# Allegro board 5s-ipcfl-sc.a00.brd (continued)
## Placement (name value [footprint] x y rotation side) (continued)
PU80  RT9045AGSP  [MX_SOIC_8P_50_201X236_PAD]  209.55 150.01 180 top
PU581  RT3607CEGQW  [MX_QFN_56P_16_S236_PAD_4V]  78.64 218.73 0 top
PU591  RT9624DGQWA  [MX_DFN_8P_20_79X79_PAD_RIC]  70.67 186.56 180 top
PU592  RT9624DGQWA  [MX_DFN_8P_20_79X79_PAD_RIC]  67.01 205.07 180 top
PU601  RT9624DGQWA  [MX_DFN_8P_20_79X79_PAD_RIC]  70.54 169.21 180 top
PU602  RT9624DGQWA  [MX_DFN_8P_20_79X79_PAD_RIC]  71.29 152.14 180 top
PU611  RT9624DGQWA  [MX_DFN_8P_20_79X79_PAD_RIC]  95.45 227.46 270 top
PU612  RT9624DGQWA  [MX_DFN_8P_20_79X79_PAD_RIC]  147.74 228.57 180 top
PU651  RT8125CGQW  [MX_DFN_10P_20_S118_PAD_R_4V]  213.36 220.98 0 top
PU681  RT9025_25PSP  [MX_SOIC_8P_50_201X236_P_NIK]  44.12 232.26 180 top
Q3  UM6K1N  [MX_SOT363]  97.03 12.32 270 top
Q4  PMBS3904  [MX_SOT23]  105.44 7.8 90 top
Q5  UM6K1N  [MX_SOT363]  104.65 12.32 270 top
Q9  PMBS3904  [MX_SOT23]  28.24 40.89 0 top
Q35  UM6K1N  [MX_SOT363]  229.79 216.15 270 top
Q53  UM6K1N  [MX_SOT363]  215.52 139.32 0 top
R18  1K  [MX_R0402_SMALL_T01]  215.54 46.02 180 top
R19  1K  [MX_R0402_SMALL_T01]  213.92 46.02 0 top
R25  300  [MX_R0603_SMALL_T01]  103 5.69 90 top
R27  300  [MX_R0603_SMALL_T01]  99.85 5.69 90 top
R30  300  [MX_R0603_SMALL_T01]  95.15 5.69 90 top
R31  300  [MX_R0603_SMALL_T01]  101.14 5.69 90 top
R36  110  [MX_R0805_SMALL_T02_H26]  31.47 41.99 90 top
R37  100  [MX_R0402_SMALL_T01]  28.17 37.97 90 top
R636  100K  [MX_R0402_SMALL_T01]  225.55 34.29 0 top
R37456  90.9K  [MX_R0402_SMALL_T01]  222.5 105.03 90 top
R60373  45.3K  [MX_R0402_SMALL_T01]  225.7 104.75 180 top
R60374  45.3K  [MX_R0402_SMALL_T01]  223.72 116.97 90 top
R60375  90.9K  [MX_R0402_SMALL_T01]  225.59 79.68 0 top
R60381  53.6K  [MX_R0402_SMALL_T01]  222.81 116.97 90 top
R60385  53.6K  [MX_R0402_SMALL_T01]  224.43 105.03 90 top
R69583  100K  [MX_R0402_SMALL_T01]  225.6 80.64 0 top
R69584  100K  [MX_R0402_SMALL_T01]  223.47 105.03 90 top
R69686  300  [MX_R0603_SMALL_T01]  98.32 5.69 90 top
R69687  300  [MX_R0603_SMALL_T01]  96.7 5.69 90 top
R69694  2.32K  [MX_R0402_SMALL_T01]  118.19 56.13 90 top
R69695  100K  [MX_R0402_SMALL_T01]  221.5 99.26 180 top
RFC14  10PF/50V  [MX_C0402_SMALL_T01]  9.19 138.86 270 top
RFC15  10PF/50V  [MX_C0402_SMALL_T01]  21.79 139.52 90 top
RFC29  10PF/50V  [MX_C0402_SMALL_T01]  173.66 106.55 90 top
RFC30  10PF/50V  [MX_C0402_SMALL_T01]  190.63 108.97 90 top
RFC31  10PF/50V  [MX_C0402_SMALL_T01]  207.8 109.22 90 top
RFC32  10PF/50V  [MX_C0402_SMALL_T01]  206.88 109.22 90 top
RFC100  10PF/50V  [MX_C0402_SMALL_T01]  208.74 143.81 0 top
RFC101  10PF/50V  [MX_C0402_SMALL_T01]  208.84 159 90 top
RFC102  10PF/50V  [MX_C0402_SMALL_T01]  206.98 102.41 270 top
RFC103  10PF/50V  [MX_C0402_SMALL_T01]  207.82 164.59 90 top
RFC104  10PF/50V  [MX_C0402_SMALL_T01]  174.65 101.27 270 top
RFC105  10PF/50V  [MX_C0402_SMALL_T01]  190.75 144.7 90 top
RFC106  10PF/50V  [MX_C0402_SMALL_T01]  207.92 158.95 90 top
RFC107  10PF/50V  [MX_C0402_SMALL_T01]  207.9 103.12 270 top
RFC108  10PF/50V  [MX_C0402_SMALL_T01]  190.53 139.01 90 top
RFC109  10PF/50V  [MX_C0402_SMALL_T01]  209.75 159 90 top
RFC110  10PF/50V  [MX_C0402_SMALL_T01]  209.75 107.21 180 top
RFC111  10PF/50V  [MX_C0402_SMALL_T01]  208.74 142.9 0 top
RFC112  10PF/50V  [MX_C0402_SMALL_T01]  53.06 75.79 0 top
RFC113  10PF/50V  [MX_C0402_SMALL_T01]  23.14 12.06 270 top
RFC114  10PF/50V  [MX_C0402_SMALL_T01]  23.98 17.4 90 top
RFC115  10PF/50V  [MX_C0402_SMALL_T01]  14.86 175.44 90 top
RFC116  10PF/50V  [MX_C0402_SMALL_T01]  226.19 196.49 180 top
RFC117  10PF/50V  [MX_C0402_SMALL_T01]  223.93 157.76 180 top
RFC118  10PF/50V  [MX_C0402_SMALL_T01]  49.29 193.13 180 top
RFC119  10PF/50V  [MX_C0402_SMALL_T01]  49.89 165.81 180 top
RFC120  10PF/50V  [MX_C0402_SMALL_T01]  38.1 191.52 0 top
RFC121  10PF/50V  [MX_C0402_SMALL_T01]  43.66 140.97 270 top
RN23  10K  [MX_4R8P0402]  204.22 32.66 90 top
RN24  10K  [MX_4R8P0402]  204.22 39.62 90 top
RN25  10K  [MX_4R8P0402]  204.22 37.08 90 top
RN26  10K  [MX_4R8P0402]  210.57 43.31 0 top
S/PDIF  OPTICAL_RCA_JACK_5P  [MX_OPTCL_JACK_5P_2H_JY_LF5]  8.16 223.89 270 top
SC6  15PF/50V  [MX_C0402_SMALL_T01]  153.39 32.11 0 top
SC7  15PF/50V  [MX_C0402_SMALL_T01]  152.15 29.62 270 top
SC8  12PF/50V  [MX_C0402_SMALL_T01]  151.33 63.22 90 top
SC9  12PF/50V  [MX_C0402_SMALL_T01]  152.22 61.59 270 top
SC32  0.22UF/10V  [MX_C0402_SMALL_T01]  62.94 66.5 270 top
SC52  15PF/50V  [MX_C0402_SMALL_T01]  221.16 21.97 90 top
SC61  0.22UF/10V  [MX_C0402_SMALL_T01]  62.03 66.5 270 top
SC62  0.22UF/10V  [MX_C0402_SMALL_T01]  66.52 66.47 270 top
SC63  0.22UF/10V  [MX_C0402_SMALL_T01]  67.44 66.47 270 top
SC64  0.1UF/16V  [MX_C0402_SMALL_T01]  18.03 162.59 0 top
SC65  0.1UF/16V  [MX_C0402_SMALL_T01]  18.03 163.5 0 top
SC66  0.1UF/16V  [MX_C0402_SMALL_T01]  18.03 164.41 0 top
SC67  0.1UF/16V  [MX_C0402_SMALL_T01]  18.03 165.33 0 top
SC68  0.1UF/16V  [MX_C0402_SMALL_T01]  18.03 166.24 0 top
SC69  0.1UF/16V  [MX_C0402_SMALL_T01]  18.03 167.16 0 top
SC70  100PF/50V  [MX_C0402_SMALL_T01]  164.72 27.43 180 top
SC72  150PF/50V  [MX_C0402_SMALL_T01]  188.47 39.75 0 top
SC80  10PF/50V  [MX_C0402_SMALL_T01]  151.51 35.43 180 top
SC81  10PF/50V  [MX_C0402_SMALL_T01]  147.96 35.43 180 top
SC82  10PF/50V  [MX_C0402_SMALL_T01]  151.51 34.49 180 top
SC83  10PF/50V  [MX_C0402_SMALL_T01]  149.48 36.58 180 top
SC85  47PF/50V  [MX_C0402_SMALL_T01]  188.47 38.72 0 top
SC86  47PF/50V  [MX_C0402_SMALL_T01]  188.47 36.75 0 top
SC90  150PF/50V  [MX_C0402_SMALL_T01]  188.47 37.81 0 top
SC100  0.1UF/6.3V  [MX_C0201]  134.69 61.72 90 top
SC101  1UF/25V  [MX_C0603_SMALL_T01]  132.27 61.47 270 top
SC102  1UF/25V  [MX_C0603_SMALL_T01]  155.49 26.47 270 top
SC103  1UF/25V  [MX_C0603_SMALL_T01]  154.14 26.49 270 top
SC105  0.1UF/16V  [MX_C0402_SMALL_T01]  148.3 39.17 0 top
SC121  0.1UF/16V  [MX_C0402_SMALL_T01]  131.93 29.34 180 top
SC141  20PF/50V  [MX_C0402_SMALL_T01]  163.25 31.47 90 top
SC146  0.1UF/16V  [MX_C0402_SMALL_T01]  148.72 46.48 180 top
SC147  20PF/50V  [MX_C0402_SMALL_T01]  165.81 24.08 0 top
SC148  0.1UF/16V  [MX_C0402_SMALL_T01]  157.53 28.83 180 top
SC149  180PF/50V  [MX_C0402_SMALL_T01]  131.57 28.02 180 top
SC152  0.1UF/16V  [MX_C0402_SMALL_T01]  18.03 168.07 0 top
SC153  0.1UF/16V  [MX_C0402_SMALL_T01]  18.03 168.99 0 top
SC154  0.22UF/10V  [MX_C0402_SMALL_T01]  74.3 66.5 270 top
SC155  0.22UF/10V  [MX_C0402_SMALL_T01]  70.87 66.47 270 top
SC156  0.22UF/10V  [MX_C0402_SMALL_T01]  75.21 66.5 270 top
SC157  0.22UF/10V  [MX_C0402_SMALL_T01]  71.78 66.47 270 top
SC158  0.22UF/10V  [MX_C0402_SMALL_T01]  67.21 46.23 270 top
SC159  0.22UF/10V  [MX_C0402_SMALL_T01]  74.3 46.1 270 top
SC160  0.22UF/10V  [MX_C0402_SMALL_T01]  63.2 46.94 270 top
SC161  0.22UF/10V  [MX_C0402_SMALL_T01]  70.23 46.1 270 top
SC162  0.22UF/10V  [MX_C0402_SMALL_T01]  64.11 46.94 270 top
SC163  0.22UF/10V  [MX_C0402_SMALL_T01]  75.21 46.1 270 top
SC164  0.22UF/10V  [MX_C0402_SMALL_T01]  66.29 46.23 270 top
SC165  0.22UF/10V  [MX_C0402_SMALL_T01]  71.15 46.1 270 top
SC166  0.01UF/50V  [MX_C0402_SMALL_T01]  227.25 112.1 0 top
SC167  0.01UF/50V  [MX_C0402_SMALL_T01]  227.53 82.83 180 top
SC168  1UF/25V  [MX_C0603_SMALL_T01]  136.3 63.1 0 top
SC170  0.1UF/16V  [MX_C0402_SMALL_T01]  24.82 229.21 270 top
SC171  1000PF/50V  [MX_C0402_SMALL_T01]  19.48 229.16 270 top
SC172  1UF/25V  [MX_C0603_SMALL_T01]  16.61 232.75 90 top
SC173  0.1UF/16V  [MX_C0402_SMALL_T01]  23.29 232.49 180 top
SC174  0.1UF/6.3V  [MX_C0201]  159.64 31.37 180 top
SC175  0.1UF/16V  [MX_C0402_SMALL_T01]  167.34 32.51 180 top
SCB1  22UF/6.3V  [MX_C0603_SMALL_T02]  198.88 61.26 270 top
SCB2  22UF/6.3V  [MX_C0603_SMALL_T02]  202.49 64.01 0 top
SCB3  1UF/6.3V  [MX_C0402_SMALL_T01]  189.08 41.53 270 top
SCB4  22UF/6.3V  [MX_C0603_SMALL_T02]  150.44 56.54 90 top
SCB5  1UF/6.3V  [MX_C0402_SMALL_T01]  152.22 56.79 90 top
SCB7  0.1UF/16V  [MX_C0402_SMALL_T01]  191.26 47.62 270 top
SCB8  22UF/6.3V  [MX_C0603_SMALL_T02]  188.98 60.2 0 top
SCB9  1UF/6.3V  [MX_C0402_SMALL_T01]  189.38 56.26 0 top
SCB10  0.1UF/6.3V  [MX_C0201]  157.11 33.45 270 top
SCB11  1UF/6.3V  [MX_C0402_SMALL_T01]  188.11 55.76 90 top
SCB12  22UF/6.3V  [MX_C0603_SMALL_T02]  191.06 65.91 270 top
SCB13  1UF/6.3V  [MX_C0402_SMALL_T01]  189.87 66.16 270 top
SCB14  22UF/6.3V  [MX_C0603_SMALL_T02]  148.54 56.54 90 top
SCB15  22UF/6.3V  [MX_C0603_SMALL_T02]  192.41 66.93 270 top
SCB16  22UF/6.3V  [MX_C0603_SMALL_T02]  200.89 58.52 0 top
SCB19  1UF/6.3V  [MX_C0402_SMALL_T01]  185.17 33.02 270 top
SCB21  0.1UF/16V  [MX_C0402_SMALL_T01]  189.99 41.53 270 top
SCB25  0.1UF/16V  [MX_C0402_SMALL_T01]  163.6 25.55 90 top
SCB28  0.1UF/6.3V  [MX_C0201]  152.73 27.05 0 top
SCB29  0.1UF/6.3V  [MX_C0201]  171.4 24.23 0 top
SCB30  1UF/6.3V  [MX_C0402_SMALL_T01]  173.38 26.9 180 top
SCB31  1UF/6.3V  [MX_C0402_SMALL_T01]  173.63 32.84 270 top
SCB32  1UF/6.3V  [MX_C0402_SMALL_T01]  175.06 32.87 270 top
SCB35  1UF/6.3V  [MX_C0402_SMALL_T01]  171.4 25.15 0 top
SCB36  0.1UF/6.3V  [MX_C0201]  177 30.3 270 top
SCB68  47PF/50V  [MX_C0402_SMALL_T01]  216.99 22.05 90 top
SCB69  47PF/50V  [MX_C0402_SMALL_T01]  209.17 22.05 90 top
SCB70  10PF/50V  [MX_C0402_SMALL_T01]  218.29 20.42 180 top
SCB75  180PF/50V  [MX_C0402_SMALL_T01]  219.71 43.29 90 top
SCB118  0.1UF/6.3V  [MX_C0201]  161.76 24.54 270 top
SCB119  68PF/50V  [MX_C0402_SMALL_T01]  215.16 22.2 90 top
SCB120  0.1UF/16V  [MX_C0402_SMALL_T01]  188.16 41.53 270 top
SCB121  10PF/50V  [MX_C0402_SMALL_T01]  198.75 10.67 180 top
SCB122  1UF/6.3V  [MX_C0402_SMALL_T01]  186.18 33.02 270 top
SHS1  HEATSINK_2ANCHOR  [MX_HSK_S1299_2ANCHOR_LF3]  170.81 50.67 90 top
SLOT1  PCI_EXPRESS_X16  [MX_SLOT_PCI_E_164P_2H_L_LF3]  57.1 81.58 0 top
SLOT2  SLOT_PCI_64P  [MX_SLOT_PCI64P_79_2HOLD_LF3]  57.1 61.26 0 top
SLOT3  SLOT_PCI_64P  [MX_SLOT_PCI64P_79_2HOLD_LF3]  57.1 40.94 0 top
SLOT4  PCI_EXPRESS_X16  [MX_SLOT_PCI_E_164P_2H_L_LF3]  57.1 20.62 0 top
SQ1  PMBS3906  [MX_SOT23]  202.57 50.95 270 top
SR1  1K  [MX_R0402_SMALL_T01]  142.63 40.91 180 top
SR2  1K  [MX_R0402_SMALL_T01]  151 48.01 180 top
SR4  0  [MX_R0402_SHORT_SMALL_T01]  164.52 25.55 270 top
SR7  10K  [MX_R0402_SMALL_T01]  231.93 20.19 90 top
SR8  10K  [MX_R0402_SMALL_T01]  230.58 18.26 90 top
SR12  0  [MX_R0603_SMALL_T01]  189.81 68.55 270 top
SR13  10K  [MX_R0402_SMALL_T01]  201.85 48.29 180 top
SR14  1K  [MX_R0402_SMALL_T01]  202.9 53.59 180 top
SR15  1K  [MX_R0402_SMALL_T01]  177.9 30.61 90 top
SR17  330  [MX_R0805_SMALL_T02]  9.65 238.25 90 top
SR18  1K  [MX_R0402_SMALL_T01]  168.86 27 270 top
SR20  10K  [MX_R0402_SMALL_T01]  142.63 41.86 0 top
SR27  15  [MX_R0402_SMALL_T01]  178.13 33.02 90 top
SR28  15  [MX_R0402_SMALL_T01]  179.04 33.02 90 top
SR29  15  [MX_R0402_SMALL_T01]  180.87 33.02 90 top
SR30  15  [MX_R0402_SMALL_T01]  179.96 33.02 90 top
SR31  15  [MX_R0402_SMALL_T01]  177.19 33.02 90 top
SR43  0  [MX_R0603_SMALL_T01]  194.89 60.53 180 top
SR44  0  [MX_R0402_SMALL_T01]  152.17 31.24 90 top
SR45  10M  [MX_R0402_SMALL_T01]  153.16 30.66 270 top
SR49  0  [MX_R0603_SMALL_T01]  191.12 68.55 270 top
SR54  0  [MX_R0603_SMALL_T01]  192.68 47.4 270 top
SR59  1M  [MX_R0402_SMALL_T01]  153.09 62.43 270 top
SR60  113  [MX_R0402_SMALL_T01]  148.72 48.01 0 top
SR70  100K  [MX_R0402_SMALL_T01]  153.16 48.01 0 top
SR75  0  [MX_R0402_SMALL_T01]  133.6 108.71 0 top
SR80  0  [MX_R0402_SHORT_SMALL_T01]  169.01 23.32 270 top
SR81  0  [MX_R0402_SHORT_SMALL_T01]  170.13 23.32 270 top
SR82  0  [MX_R0402_SHORT_SMALL_T01]  167.84 27.58 270 top
SR83  22  [MX_R0402_SMALL_T01]  160.13 24.97 90 top
SR84  22  [MX_R0402_SMALL_T01]  158.88 24.08 0 top
SR85  0  [MX_R0402_SHORT_SMALL_T01]  160.48 22.73 0 top
SR87  10K  [MX_R0402_SMALL_T01]  164.72 28.35 0 top
SR92  22  [MX_R0402_SMALL_T01]  164.16 31.47 90 top
SR94  10K  [MX_R0402_SMALL_T01]  192.02 49.09 180 top
SR100  1K  [MX_R0402_SMALL_T01]  136.39 64.86 270 top
SR101  20K  [MX_R0402_SMALL_T01]  154.05 28.12 180 top
SR102  20K  [MX_R0402_SMALL_T01]  155.68 28.12 0 top
SR115  10K  [MX_R0402_SMALL_T01]  163.91 30.2 0 top
SR119  0  [MX_R0402_SMALL_T01]  168.99 33.4 0 top
SR129  10K  [MX_R0402_SMALL_T01]  199.29 52.12 90 top
SR139  10K  [MX_R0402_SMALL_T01]  149.58 33.27 0 top
SR153  0  [MX_R0402_SMALL_T01]  80.39 111.63 45 top
SR154  0  [MX_R0402_SMALL_T01]  91.64 116.61 315 top
SR160  51  [MX_R0402_SMALL_T01]  140.21 41.02 0 top
SR162  1K  [MX_R0402_SMALL_T01]  87.18 112.06 315 top
SR164  2.2K  [MX_R0402_SMALL_T01]  84.31 109.18 315 top
SR165  2.2K  [MX_R0402_SMALL_T01]  95.38 101.09 225 top
SR166  2.2K  [MX_R0402_SMALL_T01]  94.79 97.71 90 top
SR220  30  [MX_R0402_SMALL_T01]  144.44 47.43 180 top
SR240  1K  [MX_R0402_SMALL_T01]  153.16 37.47 0 top
SR241  33  [MX_R0402_SMALL_T01]  151.51 37.01 0 top
SR242  33  [MX_R0402_SMALL_T01]  153.16 34.49 0 top
SR243  33  [MX_R0402_SMALL_T01]  153.16 36.55 0 top
SR244  22  [MX_R0402_SMALL_T01]  153.16 35.43 0 top
SR245  20  [MX_R0402_SMALL_T01]  123.9 119.91 180 top
SR246  30  [MX_R0402_SMALL_T01]  153.09 44.42 0 top
SR250  1K  [MX_R0402_SMALL_T01]  191.97 40.08 180 top
SR251  1K  [MX_R0402_SMALL_T01]  191.97 39.22 180 top
SR252  499  [MX_R0402_SMALL_T01]  191.97 37.41 180 top
SR253  499  [MX_R0402_SMALL_T01]  191.97 36.55 180 top
SR254  1K  [MX_R0402_SMALL_T01]  191.97 40.97 180 top
SR255  1K  [MX_R0402_SMALL_T01]  191.97 38.38 180 top
SR256  1K  [MX_R0402_SMALL_T01]  195.4 38.91 180 top
SR257  1K  [MX_R0402_SMALL_T01]  195.4 38.05 180 top
SR268  4.7K  [MX_R0402_SMALL_T01]  172.36 33.24 180 top
SR275  10K  [MX_R0402_SMALL_T01]  190.26 43.75 270 top
SR277  1K  [MX_R0402_SMALL_T01]  192.07 42.24 90 top
SR278  1K  [MX_R0402_SMALL_T01]  193.68 42.24 90 top
SR280  0  [MX_R0402_SMALL_T01]  153.16 39.37 0 top
SR281  30  [MX_R0402_SMALL_T01]  145.41 45.77 180 top
SR287  51  [MX_R0402_SMALL_T01]  151.33 41.91 180 top
SR289  51  [MX_R0402_SMALL_T01]  147.96 41.61 270 top
SR292  1K  [MX_R0402_SMALL_T01]  148.87 41.61 270 top
SR336  10K  [MX_R0402_SMALL_T01]  157.53 29.74 180 top
SR343  10K  [MX_R0402_SMALL_T01]  167.39 30.15 270 top
SR360  10K  [MX_R0402_SMALL_T01]  159.26 28.19 0 top
SR363  1K  [MX_R0402_SMALL_T01]  159.26 29.11 0 top
SR364  1M  [MX_R0402_SMALL_T01]  156.21 29.39 90 top
SR365  1K  [MX_R0402_SMALL_T01]  159.16 30.02 0 top
SR366  1K  [MX_R0402_SMALL_T01]  177.44 26.77 270 top
SR367  620  [MX_R0402_SMALL_T01]  150.37 46.48 180 top
SR370  4.7K  [MX_R0402_SMALL_T01]  187.53 32.49 180 top
SR371  20K  [MX_R0402_SMALL_T01]  187.53 33.4 0 top
SR375  10K  [MX_R0402_SMALL_T01]  159.26 27.28 0 top
SR400  2.71Kohm  [MX_R0402_SMALL_T01]  146.63 64.62 270 top
SR401  100  [MX_R0402_SMALL_T01]  162.41 65.74 0 top
SR411  0  [MX_R0603_SMALL_T01]  146.56 56.67 0 top
SR443  10K  [MX_R0402_SMALL_T01]  189.87 45.06 180 top
SR545  10K  [MX_R0402_SMALL_T01]  195.15 49 0 top
SR628  10K  [MX_R0402_SMALL_T01]  26.26 170.31 180 top
SR629  10K  [MX_R0402_SMALL_T01]  26.26 169.39 0 top
SR650  4.7K  [MX_R0402_SMALL_T01]  176.15 30.51 90 top
SR653  0.1UF/6.3V  [MX_C0201]  153.16 33.53 0 top
SR659  470  [MX_R0402_SMALL_T01]  131.93 30.28 0 top
SR664  100K  [MX_R0402_SMALL_T01]  153.16 38.4 0 top
SR667  10K  [MX_R0402_SMALL_T01]  195.5 55.14 90 top
SR671  10K  [MX_R0402_SMALL_T01]  193.68 55.14 90 top
SR673  10K  [MX_R0402_SMALL_T01]  198.02 55.14 90 top
SR678  10K  [MX_R0402_SMALL_T01]  183.21 31.27 180 top
SR680  10K  [MX_R0402_SMALL_T01]  171.27 30.45 90 top
SR694  1K  [MX_R0402_SMALL_T01]  146.94 48.01 180 top
SR711  10K  [MX_R0402_SMALL_T01]  189.35 53.07 0 top
SR712  10K  [MX_R0402_SMALL_T01]  189.35 54.12 0 top
SR713  10K  [MX_R0402_SMALL_T01]  55.42 115.7 180 top
SR714  10K  [MX_R0402_SMALL_T01]  55.42 114.78 180 top
SR738  10K  [MX_R0402_SMALL_T01]  158.83 22.73 0 top
SR745  22  [MX_R0402_SMALL_T01]  165.81 25.01 0 top
SR746  10K  [MX_R0402_SMALL_T01]  165.2 30.12 90 top
SR747  0  [MX_R0402_SMALL_T01]  151.33 61.59 270 top
SR749  1K  [MX_R0402_SMALL_T01]  172.21 31.88 270 top
SR758  33K  [MX_R0402_SMALL_T01]  136.05 61.97 0 top
SR759  1.1K  [MX_R0402_SMALL_T01]  136.05 60.73 180 top
SR839  10K  [MX_R0402_SMALL_T01]  213.74 22.35 180 top
SR7564  10K  [MX_R0402_SMALL_T01]  229.13 100.25 180 top
SR7565  10K  [MX_R0402_SMALL_T01]  226.36 111.18 180 top
SR7622  1.5K  [MX_R0402_SMALL_T01]  93.6 118.57 135 top
SR7627  10K  [MX_R0402_SMALL_T01]  183.23 32.35 180 top
SR7628  10K  [MX_R0402_SMALL_T01]  183.23 33.26 180 top
SR7629  10K  [MX_R0402_SMALL_T01]  172.24 29.46 270 top
SR7630  2.2K  [MX_R0402_SMALL_T01]  146.56 39.17 0 top
SR7634  0  [MX_R0402_SMALL_T01]  92.28 117.27 315 top
SR7635  0  [MX_R0402_SMALL_T01]  83.57 113.64 270 top
SR7637  100K  [MX_R0402_SMALL_T01]  131.57 27.1 180 top
SR7638  10K  [MX_R0402_SMALL_T01]  163.09 27.43 180 top
SR7642  0  [MX_R0402_SMALL_T01]  89.28 114.2 315 top
SR7643  0  [MX_R0402_SMALL_T01]  88.65 113.54 315 top
SR7646  1.5K  [MX_R0402_SMALL_T01]  165.8 25.93 0 top
SR7656  0  [MX_R0402_SMALL_T01]  165.25 31.83 90 top
SR7658  100K  [MX_R0402_SMALL_T01]  150.94 38.85 180 top
SR7659  0  [MX_R0402_SMALL_T01]  57.94 9.14 270 top
SR7660  0  [MX_R0402_SMALL_T01]  55.91 9.14 270 top
SR7664  0  [MX_R0402_SHORT_SMALL_T01]  112.38 55.64 0 top
SR7665  0  [MX_R0402_SHORT_SMALL_T01]  112.38 54.69 0 top
SR7676  10K  [MX_R0402_SMALL_T01]  223.19 101.13 0 top
SR7677  10K  [MX_R0402_SMALL_T01]  73.03 9.27 90 top
SR7678  10K  [MX_R0402_SMALL_T01]  73.95 9.27 90 top
SR7682  0  [MX_R0402_SMALL_T01]  48.9 34.42 270 top
SR7683  0  [MX_R0402_SMALL_T01]  50.16 34.42 270 top
SR7684  0  [MX_R0402_SMALL_T01]  48.74 52.93 270 top
SR7685  0  [MX_R0402_SMALL_T01]  49.66 52.93 270 top
SR7686  0  [MX_R0402_SMALL_T01]  49.53 13.94 90 top
SR7687  0  [MX_R0402_SMALL_T01]  50.65 13.94 90 top
SR7688  0  [MX_R0402_SMALL_T01]  48.11 66.04 0 top
SR7689  0  [MX_R0402_SMALL_T01]  49.76 66.04 180 top
SR7690  100K  [MX_R0402_SMALL_T01]  129.77 28.83 90 top
SR7691  0  [MX_R0402_SMALL_T01]  95.73 98.55 270 top
SR7696  10K  [MX_R0402_SMALL_T01]  191.65 54.33 180 top
SR7697  10K  [MX_R0402_SMALL_T01]  191.65 53.04 180 top
SR7698  10K  [MX_R0402_SMALL_T01]  195.15 49.94 180 top
SR7701  0  [MX_R0402_SMALL_T01]  223.19 100.18 0 top
SR7702  10K  [MX_R0402_SMALL_T01]  196.49 43.48 270 top
SR7703  10  [MX_R0402_SMALL_T01]  25.73 229.21 90 top
SR7704  1K  [MX_R0402_SMALL_T01]  19.48 230.81 270 top
SR7705  10K  [MX_R0402_SMALL_T01]  18.14 231.23 0 top
SR7706  8.2K  [MX_R0402_SMALL_T01]  17.73 233 90 top
SR7707  0  [MX_R0805_SMALL_T02]  23.34 234.39 270 top
SR7713  0  [MX_R0402_SMALL_T01]  169.01 32.33 180 top
SR7714  10K  [MX_R0402_SMALL_T01]  132.36 234.85 180 top
SR7717  0  [MX_R0402_SMALL_T01]  90.48 115.57 315 top
SR7748  1K  [MX_R0402_SMALL_T01]  194.39 45.95 0 top
SR7767  33  [MX_R0402_SMALL_T01]  59.45 9.66 0 top
SR7768  33  [MX_R0402_SMALL_T01]  76.83 9.14 90 top
SR7769  10K  [MX_R0402_SMALL_T01]  191.64 55.45 180 top
SR7776  0  [MX_R0402_SMALL_T01]  58.5 14.84 270 top
SR7777  0  [MX_R0402_SMALL_T01]  59.42 14.84 270 top
SR7778  1K  [MX_R0402_SMALL_T01]  194.34 44.65 270 top
SR7779  1K  [MX_R0402_SMALL_T01]  195.3 44.65 270 top
SR7780  33  [MX_R0402_SMALL_T01]  60.78 34.75 0 top
SR7781  0  [MX_R0402_SMALL_T01]  156.23 12.16 180 top
SR7784  10K  [MX_R0402_SMALL_T01]  196.66 55.14 90 top
SR7787  1K  [MX_R0402_SMALL_T01]  118.66 7.34 180 top
SR7788  1K  [MX_R0402_SMALL_T01]  125.64 7.34 180 top
SS4  MINI_PCI_67P  [MX_MINI_PCI_67P_20_4H_COLAY]  218.36 15.78 180 top
ST1  TPC26T  [MX_TPC26T_S4_68]  164.49 43.18 180 bottom
ST36  TPC26T  [MX_TPC26T_S4_68]  167.64 45.92 180 bottom
ST37  TPC26T  [MX_TPC26T_S4_68]  169.85 43.76 180 bottom
ST76  TPC26t  [MX_TPC26T_S4_68]  39.09 147.55 180 bottom
ST77  TPC26t  [MX_TPC26T_S4_68]  37.57 148.39 180 bottom
ST106  TPC26T  [MX_TPC26T_S4_68]  161.85 36.67 180 bottom
ST128  TPC26T  [MX_TPC26T_S4_68]  158.7 36.65 180 bottom
ST147  TPC26T  [MX_TPC26T_S4_68]  167.45 34.65 180 bottom
ST154  TPC26T  [MX_TPC26T_S4_68]  163.75 32.84 180 bottom
ST156  TPC26T  [MX_TPC26T_S4_68]  170.41 34.47 180 bottom
SW1  TACT_SWITCH_4P  [MX_SW_4P_181X126]  120.98 28.5 180 top
SW2  TACT_SWITCH_4P  [MX_SW_4P_181X126]  127.23 30.94 270 top
TC1  0.01UF/50V  [MX_C0402_SMALL_T01]  231.78 64.92 0 top
TC2  0.01UF/50V  [MX_C0402_SMALL_T01]  231.78 64.01 0 top
TC3  0.01UF/50V  [MX_C0402_SMALL_T01]  231.78 61.87 0 top
TC4  0.01UF/50V  [MX_C0402_SMALL_T01]  231.78 60.96 0 top
TC5  0.01UF/50V  [MX_C0402_SMALL_T01]  231.85 12.98 0 top
TC6  0.01UF/50V  [MX_C0402_SMALL_T01]  231.85 12.06 0 top
TC7  0.01UF/50V  [MX_C0402_SMALL_T01]  231.72 8.81 0 top
TC8  0.01UF/50V  [MX_C0402_SMALL_T01]  231.72 7.9 0 top
TC9  0.01UF/50V  [MX_C0402_SMALL_T01]  231.88 48.51 0 top
TC10  0.01UF/50V  [MX_C0402_SMALL_T01]  231.88 47.6 0 top
TC11  0.01UF/50V  [MX_C0402_SMALL_T01]  231.88 44.83 0 top
TC12  0.01UF/50V  [MX_C0402_SMALL_T01]  231.88 43.92 0 top
TC21  0.01UF/50V  [MX_C0402_SMALL_T01]  231.39 31.72 0 top
TC22  0.01UF/50V  [MX_C0402_SMALL_T01]  231.4 30.81 0 top
TC23  0.01UF/50V  [MX_C0402_SMALL_T01]  231.42 29.77 0 top
TC24  0.01UF/50V  [MX_C0402_SMALL_T01]  231.42 28.83 0 top
TUC21  10UF/6.3V  [MX_C0603_SMALL_T01]  11.4 154 180 top
TUC22  10PF/50V  [MX_C0402_SMALL_T01]  8.69 146.92 270 top
TUCE1  560UF/6.3V  [MX_CE_98_BD268_H374_37_LFH]  23.72 159.87 0 top
TUU2  G524B1T11U  [MX_SOT23_S5_H57]  40.77 200.18 270 top
U2FC1  10UF/16V  [MX_C0805_SMALL_T02]  85.95 13.11 90 top
U2FC2  0.1UF/16V  [MX_C0402_SMALL_T01]  87.64 12.26 0 top
U4  ASM1142  [MX_QFN_64P_20_S354_P_MA_12V]  36.77 144.38 90 top
U5  ASM1543  [MX_QFN_32P_16_S161_PD_8V]  18.8 147.96 90 top
U10  E2400-RIV1-RL  [MX_QFN_40P_16_S197_PD_QU_9V]  34.98 215.62 180 top
U15  STM32F070CBT6TR  [A_QFP_48P_20_283X283]  114.17 36.02 180 top
U51  TPS2546RTER  [MX_QFN_16P_20_S118_PAD_RIC]  226.33 101.85 270 top
U104  SCH5553-NU  [MX_QFP_128P_16_S630_H47]  215.14 32.64 0 top
U942691  TPS2546RTER  [MX_QFN_16P_20_S118_PAD_RIC]  224.45 113.73 270 top
UC1  15PF/50V  [MX_C0402_SMALL_T01]  32.74 137.44 180 top
UC2  AT25128B-SSHL-T  [SOIC_8P_50_197X236]  102.79 32.79 0 top
UC9  0.1UF/16V  [MX_C0402_SMALL_T01]  228.75 103.17 90 top
UC10  22UF/6.3V  [MX_C0603_SMALL_T02]  232.31 113.84 90 top
UC11  22UF/6.3V  [MX_C0603_SMALL_T02]  230.3 86.61 270 top
UC12  0.1UF/16V  [MX_C0402_SMALL_T01]  233.25 109.02 180 top
UC16  1UF/6.3V  [MX_C0402_SMALL_T01]  233.25 108.1 180 top
UC29  0.22UF/10V  [MX_C0402_SMALL_T01]  29.77 132.43 135 top
UC30  0.22UF/10V  [MX_C0402_SMALL_T01]  29.12 131.79 135 top
UC31  0.22UF/10V  [MX_C0402_SMALL_T01]  26.89 139.93 90 top
UC32  0.22UF/10V  [MX_C0402_SMALL_T01]  27.8 139.93 90 top
UC50  0.1UF/16V  [MX_C0402_SMALL_T01]  231.57 96.9 90 top
UC51  0.1UF/16V  [MX_C0402_SMALL_T01]  230.66 96.9 90 top
UC52  0.1UF/16V  [MX_C0402_SMALL_T01]  232.66 94.69 90 top
UC53  0.1UF/16V  [MX_C0402_SMALL_T01]  233.58 94.69 90 top
UC68  1UF/6.3V  [MX_C0402_SMALL_T01]  42.29 146.33 270 top
UC69  1UF/6.3V  [MX_C0402_SMALL_T01]  42.06 138.84 0 top
UC72  0.1UF/6.3V  [MX_C0201]  38.61 150.9 0 top
UC74  0.1UF/6.3V  [MX_C0201]  42.27 141.15 270 top
UC75  0.1UF/6.3V  [MX_C0201]  36.35 151.36 180 top
UC77  1UF/6.3V  [MX_C0402_SMALL_T01]  30.71 147.83 180 top
UC78  1UF/6.3V  [MX_C0402_SMALL_T01]  29.61 143.71 180 top
UC79  1UF/6.3V  [MX_C0402_SMALL_T01]  36.02 138.02 270 top
UC81  1UF/6.3V  [MX_C0402_SMALL_T01]  30.91 146 180 top
UC82  1UF/6.3V  [MX_C0402_SMALL_T01]  40.46 138.23 270 top
UC83  1UF/6.3V  [MX_C0402_SMALL_T01]  38.18 137.54 270 top
UC86  0.22UF/10V  [MX_C0402_SMALL_T01]  35.28 135.13 270 top
UC87  0.22UF/10V  [MX_C0402_SMALL_T01]  36.2 135.13 270 top
UC90  1UF/6.3V  [MX_C0402_SMALL_T01]  30.53 139.75 225 top
UC91  2.2UF/6.3V  [MX_C0603_SMALL_T01]  45.25 140.12 0 top
UC92  10UF/6.3V  [MX_C0603_SMALL_T01]  38.99 155.23 0 top
UC93  10UF/6.3V  [MX_C0603_SMALL_T01]  43.05 130.8 270 top
UC94  0.1UF/6.3V  [MX_C0201]  38.1 190.6 0 top
UC96  0.22UF/10V  [MX_C0402_SMALL_T01]  31.78 128.45 180 top
UC97  0.22UF/10V  [MX_C0402_SMALL_T01]  31.78 127.53 180 top
UC98  0.22UF/10V  [MX_C0402_SMALL_T01]  30.82 130.33 180 top
UC99  0.22UF/10V  [MX_C0402_SMALL_T01]  30.82 129.42 180 top
UC641  1UF/25V  [MX_C0603_SMALL_T01]  35.97 180.29 270 top
UC943  0.22UF/10V  [MX_C0402_SMALL_T01]  37.11 135.86 270 top
UC944  0.22UF/10V  [MX_C0402_SMALL_T01]  38.02 135.86 270 top
UC946  0.22UF/10V  [MX_C0402_SMALL_T01]  13.49 149.05 0 top
UC947  0.22UF/10V  [MX_C0402_SMALL_T01]  13.49 148.13 0 top
UC948  0.22UF/10V  [MX_C0402_SMALL_T01]  14.63 145.03 90 top
UC949  0.22UF/10V  [MX_C0402_SMALL_T01]  15.54 145.03 90 top
UC950  0.1UF/16V  [MX_C0402_SMALL_T01]  33.2 150.95 90 top
UC959  0.1UF/16V  [MX_C0402_SMALL_T01]  232.31 123.29 90 top
UC960  0.1UF/16V  [MX_C0402_SMALL_T01]  230.3 125.45 90 top
UC963  0.1UF/16V  [MX_C0402_SMALL_T01]  231.22 125.45 90 top
UC964  0.1UF/16V  [MX_C0402_SMALL_T01]  233.22 123.29 90 top
UC965  0.1UF/6.3V  [MX_C0201]  22.99 147.96 0 top
UC968  1UF/6.3V  [MX_C0402_SMALL_T01]  232.94 116.05 270 top
UC969  10PF/50V  [MX_C0402_SMALL_T01]  41.45 150.01 180 top
UC970  10PF/50V  [MX_C0402_SMALL_T01]  30.71 148.82 180 top
UC971  10PF/50V  [MX_C0402_SMALL_T01]  39.04 152.17 270 top
UC972  10PF/50V  [MX_C0402_SMALL_T01]  231.9 116.05 270 top
UC973  10PF/50V  [MX_C0402_SMALL_T01]  234.67 113.59 90 top
UC974  10PF/50V  [MX_C0402_SMALL_T01]  235.97 88.47 0 top
UC975  0  [MX_R0402_SMALL_T01]  12.14 150.06 0 top
UC976  0  [MX_R0402_SMALL_T01]  12.14 150.98 0 top
UC977  0  [MX_R0402_SMALL_T01]  12.83 146.18 0 top
UC978  0  [MX_R0402_SMALL_T01]  12.83 147.09 0 top
UC979  0  [MX_R0402_SMALL_T01]  26.89 135.4 0 top
UC980  0  [MX_R0402_SMALL_T01]  26.89 134.48 0 top
UC981  0.33uF/10V  [MX_C0402_SMALL_T01]  25.88 128.83 0 top
UC982  0.33uF/10V  [MX_C0402_SMALL_T01]  25.88 127.91 0 top
UC983  0.33uF/10V  [MX_C0402_SMALL_T01]  28.42 127.38 0 top
UC984  0.33uF/10V  [MX_C0402_SMALL_T01]  28.42 126.47 0 top
UC985  0.33uF/10V  [MX_C0402_SMALL_T01]  26.77 125.91 0 top
UC986  0.33uF/10V  [MX_C0402_SMALL_T01]  26.77 124.99 0 top
UC987  0.33uF/10V  [MX_C0402_SMALL_T01]  230.15 92.59 270 top
UC988  0.33uF/10V  [MX_C0402_SMALL_T01]  231.07 92.59 270 top
UC991  0.1UF/16V  [MX_C0402_SMALL_T01]  231.2 89.87 0 top
UC992  0.1UF/16V  [MX_C0402_SMALL_T01]  231.2 88.96 0 top
UC993  0.33uF/10V  [MX_C0402_SMALL_T01]  230.47 122.3 0 top
UC994  0.33uF/10V  [MX_C0402_SMALL_T01]  230.47 121.38 0 top
UC995  0.33uF/10V  [MX_C0402_SMALL_T01]  231.19 119.11 0 top
UC996  0.33uF/10V  [MX_C0402_SMALL_T01]  231.19 120.05 0 top
UCB1  22UF/6.3V  [MX_C0603_SMALL_T02]  9.07 140.8 90 top
UCB2  22UF/6.3V  [MX_C0603_SMALL_T02]  23.97 139.18 90 top
UCB3  22UF/6.3V  [MX_C0603_SMALL_T02]  25.41 139.18 90 top
UCB4  22UF/6.3V  [MX_C0603_SMALL_T02]  10.39 140.8 90 top
UCB5  22UF/6.3V  [MX_C0603_SMALL_T02]  21.18 217.2 0 top
UCB6  22UF/6.3V  [MX_C0603_SMALL_T02]  21.18 218.62 0 top
UCB9  0.1UF/6.3V  [MX_C0201]  24.82 193.65 90 top
UCB18  0.1UF/6.3V  [MX_C0201]  61.85 9.02 180 top
UCB19  0.1UF/6.3V  [MX_C0201]  65.91 9.02 0 top
UCB23  0.1UF/16V  [MX_C0402_SMALL_T01]  8.28 138.86 270 top
UCB24  0.1UF/6.3V  [MX_C0201]  22.83 138.94 90 top
UCB25  0.1UF/6.3V  [MX_C0201]  25.83 193.65 90 top
UCB26  0.1UF/6.3V  [MX_C0201]  69.42 9.02 0 top
UCB27  10PF/50V  [MX_C0402_SMALL_T01]  54.84 9.14 90 top
UCB28  10PF/50V  [MX_C0402_SMALL_T01]  57 9.14 90 top
UCC1  20PF/50V  [MX_C0402_SMALL_T01]  117.45 42.04 0 top
UCC2  20PF/50V  [MX_C0402_SMALL_T01]  115.42 43.13 180 top
UCC3  0.1UF/6.3V  [MX_C0201]  113.5 42.11 0 top
UCC4  0.1UF/6.3V  [MX_C0201]  107.65 31.09 270 top
UCC5  0.1UF/6.3V  [MX_C0201]  117.11 29.81 270 top
UCC6  0.1UF/6.3V  [MX_C0201]  120.5 38.3 0 top
UCC7  0.1UF/6.3V  [MX_C0201]  119 41.66 90 top
UCC8  4.7UF/6.3V  [MX_C0603_SMALL_T01]  121.01 39.45 0 top
UCC9  10UF/6.3V  [MX_C0603_SMALL_T01]  109.37 41.1 180 top
UCC10  1UF/6.3V  [MX_C0402_SMALL_T01]  111.38 42.47 90 top
UCC11  0.1UF/6.3V  [MX_C0201]  101.04 37.85 90 top
UCC12  10PF/50V  [MX_C0402_SMALL_T01]  101.96 37.95 90 top
UCC13  10PF/50V  [MX_C0402_SMALL_T01]  107.72 32.59 270 top
UCC14  10PF/50V  [MX_C0402_SMALL_T01]  107.75 34.29 90 top
UCE10  560UF/6.3V  [MX_CE_98_BD268_H374_37_LFH]  36.14 195.48 270 top
UCE11  100uF/16V  [MX_CE_100U_16V_5X11_LFH]  219.66 123.22 0 top
UCE12  100uF/16V  [MX_CE_100U_16V_5X11_LFH]  226.17 128.16 270 top
UCR3  100K  [MX_R0402_SMALL_T01]  111.56 44.12 270 top
UCR11  10K  [MX_R0402_SMALL_T01]  114.92 28.55 270 top
UCR12  10K  [MX_R0402_SMALL_T01]  115.79 28.55 270 top
UCR13  15  [MX_R0402_SMALL_T01]  107.06 35.97 180 top
UCR14  15  [MX_R0402_SMALL_T01]  107.06 36.86 180 top
UCR15  15  [MX_R0402_SMALL_T01]  104.52 37.8 180 top
UCR19  0  [MX_R0402_SMALL_T01]  121.59 36.86 0 top
UCR22  0  [MX_R0402_SMALL_T01]  112.67 43.28 90 top
UCR23  10K  [MX_R0402_SMALL_T01]  121.59 35.97 0 top
UCR24  15  [MX_R0402_SMALL_T01]  104.52 38.68 180 top
UCR25  4.7K  [MX_R0402_SMALL_T01]  102.87 28.14 0 top
UCR26  0  [MX_R0603_SMALL_T01]  121.01 40.69 180 top
UCR27  0  [MX_R0603_SMALL_T01]  108.64 42.57 0 top
UCR28  10K  [MX_R0402_SMALL_T01]  121.21 32.72 0 top
UCR29  10K  [MX_R0402_SMALL_T01]  123.04 32.72 180 top
UCR30  0  [MX_R0402_SMALL_T01]  117.2 43.13 0 top
UCR31  0  [MX_R0402_SMALL_T01]  110.59 28.14 180 top
UCR34  10K  [MX_R0402_SMALL_T01]  110.59 29.03 0 top
UCR36  0  [MX_R0402_SMALL_T01]  111.99 27.76 270 top
UCR39  10K  [MX_R0402_SMALL_T01]  112.9 27.76 90 top
UCR41  0  [MX_R0603_SMALL_T01]  123.14 38.79 270 top
UCR43  1K  [MX_R0402_SMALL_T01]  78.12 8.8 180 top
UCR44  0  [MX_R0402_SMALL_T01]  139.01 11.06 0 top
UCR45  100K  [MX_R0402_SMALL_T01]  106.75 28.95 270 top
UCR46  0  [MX_R0402_SMALL_T01]  117.59 28.28 270 top
UCR47  0  [MX_R0402_SMALL_T01]  116.74 28.28 270 top
UCR48  1K  [MX_R0402_SMALL_T01]  141.29 12.59 270 top
UD8869  MMSZ5228B_F  [MX_SOD123]  34.54 185.04 270 top
UD8878  AZ5125-01J  [MX_S0402_AMAZ_COLAY]  28.3 204.09 180 top
UD8879  AZ5125-01J  [MX_S0402_AMAZ_COLAY]  28.35 200.08 180 top
UD8880  AZ5125-01J  [MX_S0402_AMAZ_COLAY]  28.3 205.84 0 top
UD8881  AZ5125-01J  [MX_S0402_AMAZ_COLAY]  28.35 198.68 180 top
UF5  1.1A/6V  [MX_POLYSWITCH_2P_0805_H30]  62.87 11.43 270 top
UF6  1.1A/6V  [MX_POLYSWITCH_2P_0805_H30]  65.66 11.43 270 top
UF7  1.1A/6V  [MX_POLYSWITCH_2P_0805_H30]  69.49 11.35 180 top
UL7  90ohm  [MX_CHOKE_4P_49X39_TAI]  30.38 197.03 0 top
UL8  90ohm  [MX_CHOKE_4P_49X39_TAI]  30.38 195.5 0 top
UL9  90ohm  [MX_CHOKE_4P_49X39_TAI]  14.02 118.21 180 top
UL10  90ohm  [MX_CHOKE_4P_49X39_TAI]  21.51 117.17 90 top
UL22  90ohm  [MX_CHOKE_4P_49X39_TAI]  231.87 102.77 270 top
UL62  90ohm  [MX_CHOKE_4P_49X39_TAI]  14.02 119.71 180 top
UL64  90ohm  [MX_CHOKE_4P_49X39_TAI]  230.94 108 90 top
UL65  90ohm  [MX_CHOKE_4P_49X39_TAI]  27.33 180.8 0 top
UL66  90ohm  [MX_CHOKE_4P_49X39_TAI]  27.33 182.3 0 top
UL67  90ohm  [MX_CHOKE_4P_49X39_TAI]  27.3 185.6 0 top
UL68  90ohm  [MX_CHOKE_4P_49X39_TAI]  27.31 184.06 0 top
UL70  90ohm  [MX_CHOKE_4P_49X39_TAI]  232.33 131.72 270 top
UL74  90ohm  [MX_CHOKE_4P_49X39_TAI]  230.63 133.25 270 top
UL75  90ohm  [MX_CHOKE_4P_49X39_TAI]  21.97 114.6 180 top
UL76  90ohm  [MX_CHOKE_4P_49X39_TAI]  11.33 152.53 0 top
UL77  90ohm  [MX_CHOKE_4P_49X39_TAI]  27.32 137.81 270 top
UL79  90ohm  [MX_CHOKE_4P_49X39_TAI]  26.44 130.1 180 top
UL83  90ohm  [MX_CHOKE_4P_49X39_TAI]  26.44 133.23 180 top
UL84  90ohm  [MX_CHOKE_4P_49X39_TAI]  26.44 131.67 180 top
UL86  90ohm  [MX_CHOKE_4P_49X39_TAI]  12.68 144.27 0 top
UL88  90ohm  [MX_CHOKE_4P_49X39_TAI]  11.38 148.54 0 top
UL90  90ohm  [MX_CHOKE_4P_49X39_TAI]  231.22 98.94 270 top
UL91  90ohm  [MX_CHOKE_4P_49X39_TAI]  233.12 96.76 270 top
UL94  90ohm  [MX_CHOKE_4P_49X39_TAI]  230.78 127.46 270 top
UL95  90ohm  [MX_CHOKE_4P_49X39_TAI]  232.74 125.32 270 top
UR5  8.2K  [MX_R0402_SMALL_T01]  223.24 119.46 0 top
UR6  51K  [MX_R0402_SMALL_T01]  225.25 116.97 90 top
UR30  10K  [MX_R0402_SMALL_T01]  16.18 141.12 270 top
UR195  4.7K  [MX_R0402_SMALL_T01]  36.14 186.69 90 top
UR69686  12.1K  [MX_R0402_SMALL_T01]  39.55 138.2 90 top
UR69692  82K  [MX_R0402_SMALL_T01]  36.14 183.13 90 top
UR69695  4.7K  [MX_R0402_SMALL_T01]  43.76 138.84 180 top
UR69703  4.7K  [MX_R0402_SMALL_T01]  40.79 193.12 270 top
UR69704  4.7K  [MX_R0402_SMALL_T01]  41.71 193.12 270 top
UR69705  4.7K  [MX_R0402_SMALL_T01]  32.28 150.95 90 top
UR69710  10K  [MX_R0402_SMALL_T01]  19.43 142.54 270 top
UR69711  10K  [MX_R0402_SMALL_T01]  23.88 226.95 270 top
UR69714  10K  [MX_R0402_SMALL_T01]  227.72 139.47 270 top
UR69715  8.2K  [MX_R0402_SMALL_T01]  225.02 106.6 0 top
UR69716  51K  [MX_R0402_SMALL_T01]  227.51 105.41 90 top
UR69717  8.2K  [MX_R0402_SMALL_T01]  224.03 134.62 0 top
UR69718  51K  [MX_R0402_SMALL_T01]  224.03 135.56 180 top
UR69719  8.2K  [MX_R0402_SMALL_T01]  20.7 142.16 0 top
UR69720  51K  [MX_R0402_SMALL_T01]  22.05 141.43 270 top
UR69721  8.2K  [MX_R0402_SMALL_T01]  13.03 139.55 180 top
UR69722  15K  [MX_R0402_SMALL_T01]  13.03 138.63 0 top
UR69723  8.2KOHM  [MX_R0402_SMALL_T01]  36.73 200.66 270 top
UR69724  15KOhm  [MX_R0402_SMALL_T01]  37.64 200.66 90 top
UR69725  15K  [MX_R0402_SMALL_T01]  23.06 223.67 270 top
UR69726  8.2K  [MX_R0402_SMALL_T01]  24.08 223.67 90 top
UR69729  10K  [MX_R0402_SMALL_T01]  228.14 138.2 180 top
UR69730  8.2K  [MX_R0402_SMALL_T01]  228.1 131.6 180 top
UR69747  33  [MX_R0402_SMALL_T01]  233.71 137.29 90 top
UR69748  33  [MX_R0402_SMALL_T01]  238.3 88.98 180 top
URN9  0  [MX_2R4P0402]  14.02 118.21 270 top
URN10  0  [MX_2R4P0402]  21.51 117.17 180 top
URN60  0  [MX_2R4P0402]  230.94 108 180 top
URN62  0  [MX_2R4P0402]  231.87 102.77 0 top
URN126  0  [MX_2R4P0402]  30.38 195.5 90 top
URN130  0  [MX_2R4P0402]  21.97 114.6 270 top
URN131  0  [MX_2R4P0402]  14.02 119.71 270 top
URN134  0  [MX_2R4P0402]  30.38 197.03 90 top
URN137  0  [MX_2R4P0402]  27.33 180.8 90 top
URN138  0  [MX_2R4P0402]  27.33 182.3 90 top
URN139  0  [MX_2R4P0402]  27.3 185.6 90 top
URN140  0  [MX_2R4P0402]  27.31 184.06 90 top
URN143  0  [MX_2R4P0402]  230.63 133.25 0 top
URN144  0  [MX_2R4P0402]  232.33 131.72 0 top
URN148  0  [MX_2R4P0402]  11.33 152.53 90 top
URN149  0  [MX_2R4P0402]  27.32 137.81 0 top
URN151  0  [MX_2R4P0402]  26.44 130.1 270 top
URN155  0  [MX_2R4P0402]  26.44 133.23 270 top
URN156  0  [MX_2R4P0402]  26.44 131.67 270 top
URN159  0  [MX_2R4P0402]  12.68 144.27 90 top
URN161  0  [MX_2R4P0402]  11.38 148.54 90 top
URN163  0  [MX_2R4P0402]  231.22 98.94 0 top
URN164  0  [MX_2R4P0402]  233.12 96.76 0 top
URN167  0  [MX_2R4P0402]  230.78 127.46 0 top
URN168  0  [MX_2R4P0402]  232.74 125.32 0 top
UU4  IP4284CZ10-TB  [MX_ESD_10P_20_98X39_NXP]  232.77 105.69 90 top
UU5  IP4284CZ10-TB  [MX_ESD_10P_20_98X39_NXP]  232.94 134.65 270 top
UU10  ESD8504GMUTAG  [A_DFN_10P_20_98X39_ONSEM]  8.89 150.04 270 top
UU14  IP4284CZ10-TB  [MX_ESD_10P_20_98X39_NXP]  24.13 125.55 270 top
UU22  IP4284CZ10-TB  [MX_ESD_10P_20_98X39_NXP]  233.34 90.42 270 top
UU26  IP4284CZ10-TB  [MX_ESD_10P_20_98X39_NXP]  233.3 99.82 270 top
UU34  ESD8504GMUTAG  [A_DFN_10P_20_98X39_ONSEM]  10.41 144.98 270 top
UU39  ESD8504GMUTAG  [A_DFN_10P_20_98X39_ONSEM]  24.16 135.38 270 top
UU40  IP4284CZ10-TB  [MX_ESD_10P_20_98X39_NXP]  24.13 132.26 270 top
UU43  IP4284CZ10-TB  [MX_ESD_10P_20_98X39_NXP]  233.34 120.52 270 top
UU44  IP4284CZ10-TB  [MX_ESD_10P_20_98X39_NXP]  233.22 128.17 270 top
UU45  G524B1T11U  [MX_SOT23_S5_H57]  13.39 141.76 180 top
UU47  G524B1T11U  [MX_SOT23_S5_H57]  20.73 225.48 270 top
UU50  G524B1T11U  [MX_SOT23_S5_H57]  18.97 139.95 0 top
UU51  G524B1T11U  [MX_SOT23_S5_H57]  226.77 134.49 270 top
UU52  IP4284CZ10-TB  [MX_ESD_10P_20_98X39_NXP]  8.74 153.26 270 top
UU53  IP4284CZ10-TB  [MX_ESD_10P_20_98X39_NXP]  24.13 129.11 270 top
UU54  G517G1TO1U  [MX_SOT23_S5_2D4_122X67_H35]  35.69 162.43 270 top
VCB155  0.1UF/16V  [MX_C0402_SMALL_T01]  26.26 168.47 0 top
X1  20MHZ  [MX_XTAL_4P_126X98_HELE_H31]  32.69 135.2 0 top
XC1  0.22UF/10V  [MX_C0402_SMALL_T01]  62.59 86.61 270 top
XC2  0.22UF/10V  [MX_C0402_SMALL_T01]  61.67 86.61 270 top
XC3  0.22UF/10V  [MX_C0402_SMALL_T01]  65.91 86.61 270 top
XC4  0.22UF/10V  [MX_C0402_SMALL_T01]  65 86.61 270 top
XC5  0.22UF/10V  [MX_C0402_SMALL_T01]  69.85 86.61 270 top
XC6  0.22UF/10V  [MX_C0402_SMALL_T01]  68.94 86.61 270 top
XC7  0.22UF/10V  [MX_C0402_SMALL_T01]  73.91 86.61 270 top
XC8  0.22UF/10V  [MX_C0402_SMALL_T01]  73 86.61 270 top
XC9  0.22UF/10V  [MX_C0402_SMALL_T01]  79.88 86.61 270 top
XC10  0.22UF/10V  [MX_C0402_SMALL_T01]  78.97 86.61 270 top
XC11  0.22UF/10V  [MX_C0402_SMALL_T01]  83.95 86.61 270 top
XC12  0.22UF/10V  [MX_C0402_SMALL_T01]  83.03 86.61 270 top
XC13  0.22UF/10V  [MX_C0402_SMALL_T01]  87.88 86.61 270 top
XC14  0.22UF/10V  [MX_C0402_SMALL_T01]  86.97 86.61 270 top
XC15  0.22UF/10V  [MX_C0402_SMALL_T01]  91.95 86.61 270 top
XC16  0.22UF/10V  [MX_C0402_SMALL_T01]  91.03 86.61 270 top
XC33  0.1UF/16V  [MX_C0402_SMALL_T01]  55.83 66.17 0 top
XC35  100PF/50V  [MX_C0402_SMALL_T01]  58.29 86.23 0 top
XC89  0.1UF/6.3V  [MX_C0201]  57.28 75.67 0 top
XC90  0.1UF/6.3V  [MX_C0201]  42.42 76.83 180 top
XC91  0.1UF/6.3V  [MX_C0201]  53.06 76.71 0 top
XC92  100PF/50V  [MX_C0402_SMALL_T01]  56.79 26.21 270 top
XC93  0.1UF/6.3V  [MX_C0201]  54.64 14.05 270 top
XC94  0.1UF/6.3V  [MX_C0201]  52.76 14.07 270 top
XC95  0.1UF/16V  [MX_C0402_SMALL_T01]  42.42 25.4 180 top
XC112  0.22UF/10V  [MX_C0402_SMALL_T01]  62 25.78 270 top
XC113  0.22UF/10V  [MX_C0402_SMALL_T01]  61.09 25.78 270 top
XC114  0.22UF/10V  [MX_C0402_SMALL_T01]  65.81 25.78 270 top
XC115  0.22UF/10V  [MX_C0402_SMALL_T01]  64.9 25.78 270 top
XC116  0.22UF/10V  [MX_C0402_SMALL_T01]  69.88 25.78 270 top
XC117  0.22UF/10V  [MX_C0402_SMALL_T01]  68.96 25.78 270 top
XC118  0.22UF/10V  [MX_C0402_SMALL_T01]  73.94 25.78 270 top
XC119  0.22UF/10V  [MX_C0402_SMALL_T01]  73.03 25.78 270 top
XC120  0.22UF/10V  [MX_C0402_SMALL_T01]  80.04 25.78 270 top
XC121  0.22UF/10V  [MX_C0402_SMALL_T01]  79.12 25.78 270 top
XC122  0.22UF/10V  [MX_C0402_SMALL_T01]  83.97 25.78 270 top
XC123  0.22UF/10V  [MX_C0402_SMALL_T01]  83.06 25.78 270 top
XC124  0.22UF/10V  [MX_C0402_SMALL_T01]  87.12 25.78 270 top
XC125  0.22UF/10V  [MX_C0402_SMALL_T01]  88.04 25.78 270 top
XC126  0.22UF/10V  [MX_C0402_SMALL_T01]  91.82 25.78 270 top
XC127  0.22UF/10V  [MX_C0402_SMALL_T01]  90.91 25.78 270 top
XC128  0.1UF/16V  [MX_C0402_SMALL_T01]  59.78 47.36 90 top
XC129  100PF/50V  [MX_C0402_SMALL_T01]  70.36 96.14 0 top
XC130  0.1UF/16V  [MX_C0402_SMALL_T01]  70.36 95.12 0 top
XC131  10PF/50V  [MX_C0402_SMALL_T01]  56.69 76.66 0 top
XCB5  0.1UF/6.3V  [MX_C0201]  49.86 55.07 180 top
XCB6  0.1UF/6.3V  [MX_C0201]  54.99 34.92 0 top
XCE2  470uF/6.3V  [MX_CE_470U_6D3V_6D3X11_LFH]  57.78 71.12 0 top
XCE14  10PF/50V  [MX_C0402_SMALL_T01]  70.36 93.47 0 top
XCE15  470uF/6.3V  [MX_CE_470U_6D3V_6D3X11_LFH]  57.4 30.61 0 top
XCE16  270UF/16V  [MX_CE_138_BD335_H512_37_LFH]  43.43 30.57 0 top
XCE17  820UF/6.3V  [MX_CE_138_BD335_H492_37_LFH]  54.99 50.16 0 top
XDP2  BtoB_CON_60P  [MX_BTOB_60P_20_F_SAMT_NS_NP]  93.8 106.55 225 top
XR1  0  [MX_R0402_SMALL_T01]  52.43 66.55 270 top
XR2  0  [MX_R0402_SMALL_T01]  53.34 66.55 270 top
XR3  0  [MX_R0402_SMALL_T01]  56.85 55.37 0 top
XR4  0  [MX_R0402_SMALL_T01]  51.41 66.55 90 top
XR5  0  [MX_R0402_SMALL_T01]  54.74 76.71 180 top
XR8  0  [MX_R0402_SMALL_T01]  51.82 86.39 180 top
XR9  0  [MX_R0402_SMALL_T01]  53.49 86.39 180 top
XR10  0  [MX_R0402_SMALL_T01]  47.93 76.61 180 top
XR11  0  [MX_R0402_SHORT_SMALL_T01]  45.03 86.33 180 top
XR12  0  [MX_R0402_SMALL_T01]  52.2 25.91 270 top
XR13  0  [MX_R0402_SMALL_T01]  53.7 14.05 90 top
XR14  0  [MX_R0402_SMALL_T01]  49.4 25.53 180 top
XR15  0  [MX_R0402_SHORT_SMALL_T01]  45.85 25.53 180 top
XR16  0  [MX_R0402_SMALL_T01]  50.8 25.91 270 top
XR17  0  [MX_R0402_SMALL_T01]  51.1 46.25 270 top
XR18  0  [MX_R0402_SMALL_T01]  50.19 46.25 270 top
XR19  0  [MX_R0402_SMALL_T01]  57.28 34.8 0 top
XR20  0  [MX_R0402_SMALL_T01]  49.28 46.25 90 top
XU1  SOCKET_1151P  [MX_SOCKET1151_FOXN_7HD]  125.45 161.46 90 top
Y5  32.768KHZ  [MX_XTAL_4P_272X55]  147.22 30 180 top
Y10  25MHZ  [MX_XTAL_4P_126X98_HOSON_H35]  31.06 224.87 180 top
Y18  24MHZ  [MX_XTAL_4P_126X98_HELE]  149.1 62.43 270 top
Y19  24MHZ  [MX_XTAL_4P_126X98_HELE]  116.61 45.42 0 top

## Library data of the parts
AC1-AC4 AC14-AC27 AC39 AC47 AC52 AC55 AC71-AC77 AC129 AC130 AC136 AC161-AC164 AC173-AC188 AC193-AC198 C1 C2 C5 C81-C83 C85 C93 C414-C417 C9357 C941399-C941401 CB2 CB4107 CB4112-CB4117 CB4119 CB4122-CB4129 D4C1-D4C5 D4C7 D4C8 D4C12 D4C13 D4C17 D4C18 D4C21-D4C24 D4CB1-D4CB41 D4CB48-D4CB55 D4CB57-D4CB78 D4CB86-D4CB89 EC22 ECC55 ECC56 F3CB1 F3CB3 F3CB4 FC2 FC3 FC5 FC6 FC8 FC13-FC16 FCE1 FCE4 FCE5 HC3-HC5 HC11 HC23-HC25 HC27 HC29-HC31 LC4-LC8 LC12 LC18 LC44 LCB2-LCB7 LCB9-LCB22 M1C1 M1C12 M1C13 M1C35 M2C1-M2C6 M2C13-M2C21 M2C44 M2C46-M2C55 O2C1 O2C2 O2C4 O2C5 O2CB1-O2CB8 O2CB10-O2CB12 O2CB15-O2CB17 O2CB19 O2CB20 P1C2 P1CB1-P1CB5 P1CB8 P1CB10-P1CB17 PC1-PC13 PC15 PC118 PC121 PC122 PC126 PC131-PC133 PC137 PC138 PC142 PC149-PC164 PC193 PC194 PC205-PC215 PC217 PC218 PC231-PC234 PC236 PC238-PC243 PC247 PC272-PC274 PC329 PC331-PC335 PC339 PC341 PC343 PC481 PC486 PC566-PC570 PC601-PC620 PC642 PC661 PC832 PC834 PC5801-PC5830 PC5901-PC5920 PC6101-PC6120 PC6201-PC6244 PC6501 PC6502 PC6521-PC6527 PC6805 PC6807-PC6810 PC640625-PC640630 PC640632-PC640637 PC640639 PC640641 PC640644-PC640649 PC640651 PC640653 PC640656 PC640658 PC640660-PC640665 PC640667 PC640671 PC640672 PC640674-PC640676 PC640679 PC640681-PC640692 RFC14 RFC15 RFC29-RFC32 RFC100-RFC121 SC6-SC9 SC52 SC70 SC72 SC80-SC83 SC85 SC86 SC90 SC100-SC103 SC105 SC121 SC141 SC146-SC149 SC166-SC168 SC170-SC175 SCB1-SCB5 SCB7-SCB16 SCB19 SCB21 SCB25 SCB28-SCB32 SCB35 SCB36 SCB68-SCB70 SCB75 SCB118-SCB122 SR653 TUC21 TUC22 U2FC1 U2FC2 UC1 UC9-UC12 UC16 UC68 UC69 UC72 UC74 UC75 UC77-UC79 UC81-UC83 UC90-UC94 UC641 UC950 UC965 UC968-UC974 UCB1-UCB6 UCB9 UCB18 UCB19 UCB23-UCB28 UCC1-UCC14 VCB155 XC33 XC35 XC89-XC95 XC128-XC131 XCB5 XCB6 XCE14 = C
AC165-AC172 ACE3-ACE7 D4CE4 PC483 PC640631 PCE11-PCE14 PCE17 PCE18 PCE23 PCE591 PCE601 PCE611 PCE651-PCE653 PCE6201-PCE6212 TUCE1 UCE10-UCE12 XCE2 XCE15-XCE17 = CAP
AD1 FD3 FD7 FD9 = BAT54AW
AD2-AD23 M1D1 UD8878-UD8881 = VPORT_0603
AL1-AL6 = BEAD: signal model: MX_R0603_SMALL_T01_0
AL7-AL18 L1 L2 = BEAD
AMB_Q1 ECQ12 ECQ13 GFX_Q1 PQ115 PQ9779 Q4 Q9 = NPN_SOT23
APR13 APR112 AR1-AR4 AR7-AR15 AR17-AR20 AR25 AR26 AR50 AR53 AR55 AR56 AR61-AR64 AR199-AR229 AR231 AR232 AR237 AR238 AR241-AR244 AR247 AR263 ASR7 CR19 D4R1 D4R3 D4R10 D4R15 D4R20 D4R21 D4R24 D4R30-D4R35 ECR67 ECR90 ECR92 ECR96-ECR98 ECR101 ECR104 ECR105 F3R3 F3R6 F3R10 F3R12 F3R13 FR1 FR2 FR8 FR28-FR32 FR35-FR37 HR9 HR11 HR14 HR15 HR23-HR25 HR29 HR32 HR33 HR36 HR615-HR622 HR626 HR627 HR629-HR631 LR1-LR6 LR9 LR10 LR22-LR24 M1R4 M1R5 M1R8 M1R11-M1R13 M1R36 M1R37 M1R40 M2R1 M2R36 M2R39 M2R46 M2R47 M2R52 M2R54 MR41 O2R1-O2R3 O2R5 O2R8 O2R10 O2R11 O2R20-O2R22 O3R5 OR3 OR5 OR6 OR22 OR29 OR34 OR35 OR37 OR44 OR51-OR53 OR56 OR57 OR59-OR61 OR65 OR68-OR70 P1R1 P1R3 P1R4 PR2-PR9 PR11 PR12 PR14 PR115 PR121-PR124 PR127-PR129 PR132-PR139 PR162 PR164 PR167 PR168 PR170-PR172 PR174 PR175 PR187-PR189 PR191-PR193 PR195 PR198 PR199 PR234-PR236 PR244 PR245 PR248 PR249 PR302 PR305 PR312 PR317 PR340 PR341 PR381 PR432 PR511 PR512 PR601-PR606 PR608-PR613 PR621-PR624 PR641 PR5801-PR5860 PR5862-PR5884 PR5901-PR5906 PR5908-PR5913 PR6101-PR6106 PR6108-PR6113 PR6506 PR6601-PR6603 PR6605 PR6607-PR6611 PR6806 PR6807 PR6809 PR6810 PR70176 PR70188-PR70190 PR70193-PR70196 PR70198 PR70199 PR70201-PR70206 PR70210-PR70213 PR70215-PR70217 PR70219-PR70223 PR70225 PR70227 PR70228 PR70231 PR70238 PR70244-PR70246 PR70250 PR70254 PR70256 PR70260 PR70261 PR70291 PR70296 PR70298 R18 R19 R25 R27 R30 R31 R36 R37 R636 R37456 R60373-R60375 R60381 R60385 R69583 R69584 R69686 R69687 R69694 R69695 SR1 SR2 SR7 SR8 SR12-SR15 SR17 SR18 SR20 SR27-SR31 SR43 SR45 SR49 SR54 SR59 SR60 SR70 SR75 SR87 SR94 SR100-SR102 SR115 SR129 SR139 SR160 SR162 SR164-SR166 SR240 SR250-SR257 SR268 SR275 SR277 SR278 SR287 SR289 SR292 SR336 SR343 SR360 SR363-SR367 SR370 SR371 SR375 SR400 SR401 SR443 SR545 SR628 SR629 SR650 SR659 SR664 SR667 SR671 SR673 SR678 SR680 SR694 SR711-SR714 SR738 SR745 SR746 SR749 SR758 SR759 SR839 SR7564 SR7565 SR7622 SR7627-SR7630 SR7634 SR7635 SR7637 SR7638 SR7642 SR7643 SR7646 SR7656 SR7658-SR7660 SR7676-SR7678 SR7682-SR7691 SR7696-SR7698 SR7701-SR7707 SR7713 SR7714 SR7717 SR7748 SR7767-SR7769 SR7776-SR7781 SR7784 SR7787 SR7788 UCR3 UCR11-UCR15 UCR19 UCR22-UCR31 UCR34 UCR36 UCR39 UCR41 UCR43-UCR48 UR5 UR6 UR30 UR195 UR69686 UR69692 UR69695 UR69703-UR69705 UR69710 UR69711 UR69714-UR69726 UR69729 UR69730 UR69747 UR69748 XR1-XR4 XR12-XR14 XR16-XR20 = R
AQ1 AQ2 AQ16-AQ18 = HBN2444S6R
AQ11 AQ13 AQ14 AQ23 SQ1 = PNP_SOT23
AR5 AR6 AR23 F3R4 FR17 FR33 HR20 HR22 HR26 M2R4 M2R33 M2R34 PR130 PR313 SR44 SR83 SR84 SR119 SR153 SR154 SR280 XR5 XR8-XR10 = R: signal model: MX_R0402_SMALL_T01_0
AR16 = R: signal model: MX_R0402_SMALL_T01_22_OHM
AR57 = R: signal model: MX_R0603_SMALL_T01_0_OHM
AR233 AR235 CR17 ECR103 F3R7 F3R8 F3R14 F3R20 F3R21 LR20 M2R40 M2R41 M2R43-M2R45 PR196 PR70207 PR70224 PR70249 SR4 SR7664 SR7665 XR15 = MX_R_SHORT
AU1 = ALC3861_CG_41
BKPT1 = BACKPLANE_7P
BUMPER1-BUMPER4 = Ant_pad_rd9
C941402 = C: room: AUD
CLIP3 CLIP4 = ANCHOR
CON4 = POWER_CON_24P
CON_CBAT = BATT_HOLDER
CON_XMM1-CON_XMM4 = DDR4_DIMM_288P_3HOLD_FOX
CR2 CR7 CR9 CR15 CR25-CR27 = LED
D20 FD1 FD8 FD10 = Dual_Diode_3cathode
E16 = HEADER_2X6P_K6
F3U1 = W25Q32FVSSIG
F3U2 = 25VF512_0
GPU_PWR = PWR_2X4P_2HOLD_CVILUX
H1-H5 = SCREWHOLE_160_ASUS
H6-H8 = MX_SCREWHOLE_87
H13-H16 H20-H23 = SCREWHOLE_SMT
HR4 HR6 = R: signal model: MX_R0402_SMALL_T01_24_9
HR17 HR18 HR70 SR80-SR82 SR85 XR11 = MX_R_SHORT: signal model: MX_R0402_SMALL_T01_0
HR27 HR78 = R: signal model: MX_R0402_SMALL_T01_20
HR28 SR241-SR246 = R: signal model: MX_R0402_SMALL_T01_33
HR31 P1R2 = R: signal model: MX_R0402_SMALL_T01_49_9
HR86 SR220 SR281 = R: signal model: MX_R0402_SMALL_T01_30
HT34 HT45-HT51 HT56 PT1-PT15 PT21-PT60 PT265-PT274 ST1 ST36 ST37 ST106 ST128 ST147 ST154 ST156 = MX_TP
J9 = JACK_USB_22P_8HLD_STD_1
J10 = USB_CON_16P_FOXCONN
J60 = MINI_PCI_67P_4H_LOTS
J83 = PHONE_JACK_26P_4H_LOTES
J125 = DISPLAYP_CON_20P_4HD_FOX
J133 = USBX4_36P_6HOLD_LOTE
J_TYPEC = USB_CON_2x12P_8HOLD_AN
LC9 LC10 LC47 LC48 UC29-UC32 UC50-UC53 UC96-UC99 UC959 UC960 UC963 UC964 UC987 UC988 UC991-UC996 = C: signal model: C_MX_C0402_SMALL_T01_0.1UF/16V_0.1UF/16V
M1F1 UF6 UF7 = POLY_FUSE
M1U1-M1U9 UU4 UU5 UU14 UU22 UU26 UU40 UU43 UU44 UU52 UU53 = IP4281CZ10
M2C22-M2C29 M2C40 M2C41 SC32 SC61-SC63 SC154-SC165 XC1-XC16 XC112-XC127 = C: signal model: C_MX_C0603_SMALL_T01_0.22UF/10V_0.22UF/10V
MQ4 MQ15 MQ18 MQ22 PQ2 PQ10 PQ23 PQ60 PQ80 PQ9777 PQ9784 PQ9787 = N_MOS_SOT23
MQ8 MQ10 MQ12 MQ19-MQ21 MQ24-MQ26 MQ28 MQ29 MQ35 PQ11 Q3 Q5 Q35 Q53 = UM6K1N_NB
MQ23 PQ37 PQ54 PQ691 PQ9786 = P_MOS_AP2325
O2Q6 = HN1C01FU
P3 = POWER_CON_4P_HOLD_FXCN
P7 = BUZZER
P17 P217 = HEADER_1X3P
P23 = HEADER_2X5P_K8
P24 P150 = BOX_HD_2X10P_K20_STD
P29 P461 = WAFER_HD_4P_HOLD_PRX
P61-P64 = MX_SATA_CON_7P_2HOLD_COMAX
P70 P458 = MX_WAFER_HD_4P_HOLD
P118 = FPC_CON_12P_2HOLD_KEC
P189 = WAFER_HD_12P_HOLD
P215 P216 = HEADER_1X2P
P311 = HEADER_1X5P_IR
P312 = HEADER_1X4P
P_HDDFAN = ZIF_CON_4P_6905
PC484 PC485 = C: room: +VTT_DDR
PCH = KABYLAKE
PD1-PD3 = SCHOTTKY_DIODE
PJP9-PJP12 PJP17 PJP19 PJP20 PJP25 PJP591-PJP595 PJP611-PJP615 PJP652 = MX_SHORT_PIN_SC
PJP621-PJP624 = SHORT_PIN_SC
PL1 PL12 PL13 PL591 PL592 PL601 PL602 PL611 PL612 PL631 PL652 PL661 = INDUCTOR
PQ19 PQ591-PQ596 PQ601-PQ606 PQ611-PQ616 PQ651-PQ653 = MX_SI7840DP_9V
PQ28-PQ30 = PMPB20EN
PQ31 = P_MOS_SOT23
PQ33 = AMS1085CD
PQ34 PQ56 = SI7840DP
PQ40 = SIZ300DT_T1_GE3
PQ46 = RN47A4
PR125 PR126 = R: room: +VTT_DDR
PR131 = R: signal model: MX_R1206_10_OHM
PR161 = R: signal model: MX_R0805_SMALL_T02_2_2_OHM
PR163 = R: signal model: MX_R0805_SMALL_T02_0_OHM
PR165 = R: signal model: MX_R0805_SMALL_T02_2_2
PR166 = R: signal model: MX_R1206_1
PR173 = R: signal model: MX_R0402_SMALL_T01_0_OHM
PR194 = MX_R_SHORT: signal model: MX_R0402_SMALL_T01_0_OHM
PRT581-PRT584 = THERMISTOR
PU5 = APL5611CI
PU7 = MX_RT8068AZQW_2
PU9 = MX_RT8237EZQW_4VIA
PU10 PU651 = RT8125CGQW_0
PU12 = RT9406GV8
PU80 = RT9173CPSP
PU581 = RT3607CEGQW_4VIA
PU591 PU592 PU601 PU602 PU611 PU612 = RT9612BGQW_0
PU681 = GS7105SO_2
RN23-RN26 = 4R8Ps
S/PDIF = OPTICAL_RCA_JACK_5P_2HOLD_JY
SC64-SC69 SC152 SC153 = C: signal model: C_MX_C0402_SMALL_T01_0.1UF/6.3V_0.1UF/6.3V
SHS1 = HEATSINK_2ANCHOR
SLOT1 SLOT4 = PCI_EXPRESS_X16_SLOT
SLOT2 SLOT3 = PCI_EXPRESS_X4
SR92 = R: signal model: MX_R0402_SMALL_T01_15
SR411 = R: signal model: MX_R0603_SMALL_T01_0
SR747 = R: signal model: R_MX_R0402_SMALL_T01_0_0
SS4 = MINI_PCI_67P_4H_LOTES_10
ST76 ST77 = test_point
SW1 SW2 = TACT_SWITCH_4P_ALP
TC1-TC12 TC21-TC24 = C: signal model: C_MX_C0402_SMALL_T01_0.01UF/25V_0.01UF/25V
TUU2 UU45 UU47 UU50 UU51 = G524D1T11U
U4 = ASM1142_12V
U5 = ASM1543_0
U10 = AR8161_BL3A_RL_9V
U15 = STM32F070CBT6_32
U51 U942691 = MX_TPS2543RTER_TI
U104 = SCH5553_NU_SMSC
UC2 = AT25HP512
UC86 UC87 UC943 UC944 UC946-UC949 = C: signal model: C_MX_C0402_0.22UF/6.3V_0.22UF/6.3V
UC975-UC980 = R: signal model: C_MX_C0402_SMALL_T01_0.22UF/10V_0.22UF/10V
UC981-UC986 = C: signal model: C_MX_C0402_SMALL_T01_0.22UF/10V_0.22UF/10V
UD8869 = Zener_Diode
UF5 = POLY_FUSE: signal model: MX_POLYSWITCH_2P_0805_H30_2_6A_6V
UL7-UL10 UL22 UL62 UL64-UL68 UL74-UL77 UL79 UL83 UL84 UL86 UL88 UL90 UL91 UL94 UL95 = Common_Choke_12_43_WE
UL70 = Common_Choke_12_43_WE: signal model: COMMON_CHOKE_12_43_WE_MX_CHOKE__90ohm
URN9 URN10 URN60 URN62 URN126 URN130 URN131 URN134 URN137-URN140 URN143 URN149 URN151 URN155 URN156 URN159 URN161 URN163 URN164 URN167 URN168 = 2R4Ps: signal model: MX_2R4P0603_0
URN144 = 2R4Ps
URN148 = 2R4Ps: signal model: 2R4PS_MX_2R4P0402_0_0
UU10 UU34 UU39 = ESD7504MUTAG
UU54 = G517C2T11U
X1 Y10 Y18 Y19 = CRYSTAL_SMD_24GND
XDP2 = BTOB_CON_60P_2HOLD_TY
XU1 = MX_AZIF0049_P001C_7HD_COF_5
Y5 = CRYSTAL_SMD_23GND

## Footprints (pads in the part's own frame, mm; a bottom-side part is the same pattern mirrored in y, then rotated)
A_DFN_10P_20_98X39_ONSEM
  rect 0.254x0.508 smd: 1(-1,-0.4) 5(1,-0.4) 6(1,0.4) 10(-1,0.4)
  rect 0.241x0.508 smd: 2(-0.5,-0.4) 4(0.5,-0.4) 7(0.5,0.4) 9(-0.5,0.4)
  rect 0.406x0.508 smd: 3(0,-0.4) 8(0,0.4)
A_QFP_48P_20_283X283
  rect 0.279x1.499 smd: 1(-2.75,-4.36) 2(-2.25,-4.36) 3(-1.75,-4.36) 4(-1.25,-4.36) 5(-0.75,-4.36) 6(-0.25,-4.36) 7(0.25,-4.36) 8(0.75,-4.36) 9(1.25,-4.36) 10(1.75,-4.36) 11(2.25,-4.36) 12(2.75,-4.36) 25(2.75,4.36) 26(2.25,4.36) 27(1.75,4.36) 28(1.25,4.36) 29(0.75,4.36) 30(0.25,4.36) 31(-0.25,4.36) 32(-0.75,4.36) 33(-1.25,4.36) 34(-1.75,4.36) 35(-2.25,4.36) 36(-2.75,4.36)
  rect 1.499x0.279 smd: 13(4.36,-2.75) 14(4.36,-2.25) 15(4.36,-1.75) 16(4.36,-1.25) 17(4.36,-0.75) 18(4.36,-0.25) 19(4.36,0.25) 20(4.36,0.75) 21(4.36,1.25) 22(4.36,1.75) 23(4.36,2.25) 24(4.36,2.75) 37(-4.36,2.75) 38(-4.36,2.25) 39(-4.36,1.75) 40(-4.36,1.25) 41(-4.36,0.75) 42(-4.36,0.25) 43(-4.36,-0.25) 44(-4.36,-0.75) 45(-4.36,-1.25) 46(-4.36,-1.75) 47(-4.36,-2.25) 48(-4.36,-2.75)
